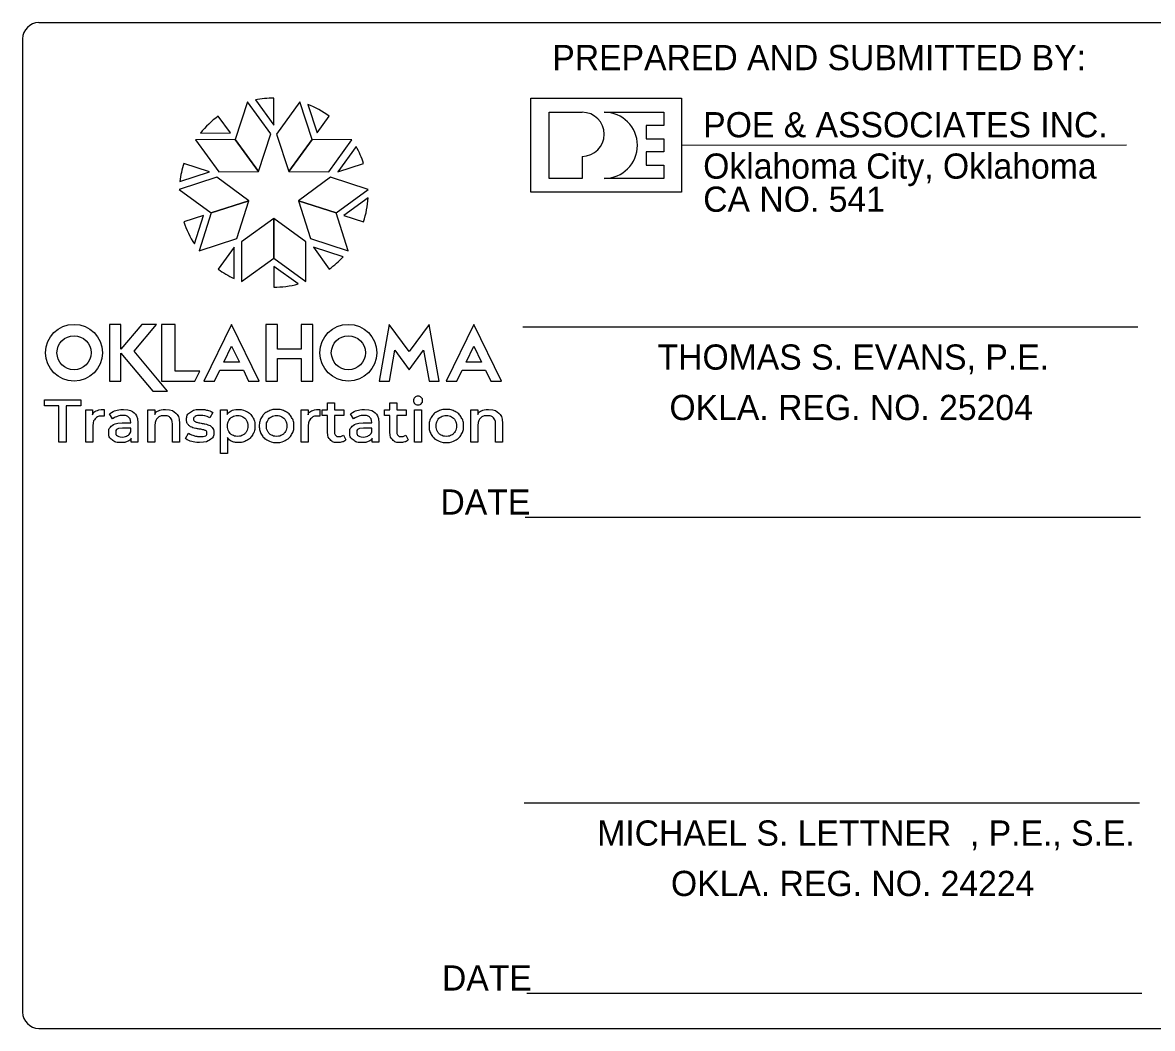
# Model space of a CAD drawing. Extents: x 2121385 to 2181200, y 132498 to 161273.
# Drawn here: x 2158768 to 2164147, y 136441 to 141232 of the extents above; entities that cross this region are included whole.
import ezdxf

# ---------------------------------------------------------------- set-up
doc = ezdxf.new("R2010")
doc.units = 0
for name, color, linetype in [('SHT_Standard_Sheet_Lines', 7, 'Continuous'), ('SHT_Standard_Sheet_Txt', 7, 'Continuous'), ('SHT_Title_Sheet_Misc', 7, 'Continuous')]:
    doc.layers.add(name, color=color, linetype=linetype)

msp = doc.modelspace()

# ---------------------------------------------------------------- linework, layer by layer
at = {"layer": 'SHT_Standard_Sheet_Lines'}
for p, q in [((2158845.7, 141231.8), (2166182.5, 141231.8)), ((2158768.1, 141154.2), (2158768.1, 136518.8)), ((2161149.1, 139783.2), (2164078.2, 139783.2)), ((2161161.2, 138876.8), (2164090.3, 138876.8)), ((2161156.2, 137516), (2164085.4, 137516)), ((2161168.3, 136609.7), (2164097.5, 136609.7)), ((2158845.7, 136441.1), (2166182.5, 136441.1))]:
    msp.add_line(p, q, dxfattribs=at)
for centre, start, end in [((2158845.7, 141154.2), 90, 180), ((2158845.7, 136518.8), 180, 270)]:
    msp.add_arc(centre, 77.6, start, end, dxfattribs=at)
at = {"layer": 'SHT_Standard_Sheet_Txt'}
for p, q in [((2161187.9, 140871.8), (2161904.6, 140871.8)), ((2161187.9, 140423.9), (2161187.9, 140871.8)), ((2161904.6, 140871.8), (2161904.6, 140423.9)), ((2161904.6, 140423.9), (2161187.9, 140423.9))]:
    msp.add_line(p, q, dxfattribs=at)
at = {"layer": 'SHT_Title_Sheet_Misc'}
for p, q in [((2159839, 140854.2), (2159780, 140674.5)), ((2159949.9, 140701.5), (2159839, 140854.2)), ((2159876.5, 140863.3), (2159963.6, 140743.3)), ((2159963.6, 140743.3), (2159963.6, 140871.8)), ((2160088.3, 140854.2), (2159977.5, 140701.1)), ((2160147.3, 140674.5), (2160088.3, 140854.2)), ((2160125.5, 140841.6), (2160170.1, 140706)), ((2159757.2, 140706), (2159699.1, 140785.8)), ((2160170.1, 140706), (2160228.1, 140785.8)), ((2161275, 140804.8), (2161432.5, 140804.8)), ((2161275, 140489.8), (2161275, 140804.8)), ((2161537.5, 140804.8), (2161821, 140804.8)), ((2161821, 140804.8), (2161821, 140741.8)), ((2161821, 140741.8), (2161737, 140741.8)), ((2161737, 140741.8), (2161737, 140678.8)), ((2159780, 140674.5), (2159590.9, 140673.9)), ((2159590.9, 140673.9), (2159701.8, 140521.3)), ((2159614.4, 140705.5), (2159757.2, 140706)), ((2159780, 140674.5), (2159890.9, 140521.9)), ((2159890.9, 140521.9), (2159780, 140674.5)), ((2159890.9, 140521.9), (2159949.9, 140701.5)), ((2159977.5, 140701.1), (2160036.4, 140521.9)), ((2160147.3, 140674.5), (2160036.4, 140521.9)), ((2160036.4, 140521.9), (2160147.3, 140674.5)), ((2160336.4, 140673.9), (2160147.3, 140674.5)), ((2160225.5, 140521.3), (2160336.4, 140673.9)), ((2161737, 140678.8), (2161821, 140678.8)), ((2161821, 140678.8), (2161821, 140615.8)), ((2160356.6, 140641.1), (2160269.5, 140521.1)), ((2161821, 140615.8), (2161737, 140615.8)), ((2161737, 140615.8), (2161737, 140552.8)), ((2161909.1, 140648.7), (2164023.6, 140649.5)), ((2159657.8, 140521.1), (2159535.7, 140560.8)), ((2160269.5, 140521.1), (2160391.6, 140560.8)), ((2161432.5, 140594.8), (2161432.5, 140489.8)), ((2159516.8, 140475.3), (2159657.8, 140521.1)), ((2159701.8, 140521.3), (2159890.9, 140521.9)), ((2160036.4, 140521.9), (2160225.5, 140521.3)), ((2161737, 140552.8), (2161821, 140552.8)), ((2161821, 140552.8), (2161821, 140489.8)), ((2159693.3, 140495.2), (2159513.9, 140436.9)), ((2159846, 140383.5), (2159693.3, 140495.2)), ((2160233.6, 140494.9), (2160081.3, 140383.5)), ((2160413.4, 140436.9), (2160233.6, 140494.9)), ((2161432.5, 140489.8), (2161275, 140489.8)), ((2161821, 140489.8), (2161537.5, 140489.8)), ((2159513.9, 140436.9), (2159666.5, 140325.2)), ((2160260.8, 140325.2), (2160413.4, 140436.9)), ((2159666.5, 140325.2), (2159846, 140383.5)), ((2159846, 140383.5), (2159666.5, 140325.2)), ((2159788.2, 140203.9), (2159846, 140383.5)), ((2160260.8, 140325.2), (2160081.3, 140383.5)), ((2160081.3, 140383.5), (2160139.2, 140203.5)), ((2160081.3, 140383.5), (2160260.8, 140325.2)), ((2160413, 140397.5), (2160297.7, 140313.2)), ((2159629.6, 140313.2), (2159535.7, 140282.7)), ((2159585.9, 140177.3), (2159629.6, 140313.2)), ((2159666.5, 140325.2), (2159608.7, 140145.2)), ((2159963.6, 140298), (2159810.3, 140187.4)), ((2159963.6, 140109.3), (2159963.6, 140298)), ((2160116.6, 140187.6), (2159963.6, 140298)), ((2159963.6, 140298), (2159963.6, 140109.3)), ((2160318.6, 140145.2), (2160260.8, 140325.2)), ((2160297.7, 140313.2), (2160391.6, 140282.7)), ((2159608.7, 140145.2), (2159788.2, 140203.9)), ((2159810.3, 140187.4), (2159810.3, 139998.7)), ((2160117, 139998.7), (2160116.6, 140187.6)), ((2160139.2, 140203.5), (2160318.6, 140145.2)), ((2159774.6, 140161.6), (2159699.1, 140057.7)), ((2159774.6, 140013.4), (2159774.6, 140161.6)), ((2160293.6, 140115.8), (2160152.6, 140161.6)), ((2160152.6, 140161.6), (2160228.1, 140057.7)), ((2159810.3, 139998.7), (2159963.6, 140109.3)), ((2159963.6, 140109.3), (2160117, 139998.7)), ((2160079.5, 139986.9), (2159963.6, 140070.5)), ((2159963.6, 140070.5), (2159963.6, 139971.8)), ((2159235.3, 139794.6), (2159181.3, 139794.6)), ((2159181.3, 139794.6), (2159181.3, 139524.5)), ((2159335.1, 139794.6), (2159235.3, 139675.7)), ((2159235.3, 139675.7), (2159235.3, 139794.6)), ((2159298.5, 139666.9), (2159405.6, 139794.6)), ((2159405.6, 139794.6), (2159335.1, 139794.6)), ((2159429.8, 139794.6), (2159429.8, 139524.5)), ((2159494.7, 139794.6), (2159429.8, 139794.6)), ((2159494.7, 139572), (2159494.7, 139794.6)), ((2159763.2, 139794.6), (2159631.5, 139524.5)), ((2159895, 139524.5), (2159763.2, 139794.6)), ((2159982, 139794.6), (2159925.8, 139794.6)), ((2159925.8, 139794.6), (2159925.8, 139524.5)), ((2159982, 139675.7), (2159982, 139794.6)), ((2160150.5, 139794.6), (2160094.3, 139794.6)), ((2160094.3, 139794.6), (2160094.3, 139675.7)), ((2160150.5, 139524.5), (2160150.5, 139794.6)), ((2160513.5, 139794.6), (2160465.9, 139524.5)), ((2160608.6, 139664.9), (2160513.5, 139794.6)), ((2160703.7, 139794.6), (2160608.6, 139664.9)), ((2160751.4, 139524.5), (2160703.7, 139794.6)), ((2160916.1, 139794.6), (2160784.3, 139524.5)), ((2161047.8, 139524.5), (2160916.1, 139794.6)), ((2159235.3, 139524.5), (2159235.3, 139658.1)), ((2159235.3, 139658.1), (2159387.4, 139476.9)), ((2159457.9, 139476.9), (2159298.5, 139666.9)), ((2159726.3, 139615.2), (2159763.2, 139690.9)), ((2159763.2, 139690.9), (2159800.1, 139615.2)), ((2160094.3, 139675.7), (2159982, 139675.7)), ((2160514.2, 139524.5), (2160540.2, 139671.8)), ((2160540.2, 139671.8), (2160608.6, 139578.5)), ((2160608.6, 139578.5), (2160677.1, 139671.8)), ((2160677.1, 139671.8), (2160703.1, 139524.5)), ((2160879.2, 139615.2), (2160916.1, 139690.9)), ((2160916.1, 139690.9), (2160953, 139615.2)), ((2159800.1, 139615.2), (2159726.3, 139615.2)), ((2159982, 139524.5), (2159982, 139632.5)), ((2159982, 139632.5), (2160094.3, 139632.5)), ((2160094.3, 139632.5), (2160094.3, 139524.5)), ((2160953, 139615.2), (2160879.2, 139615.2)), ((2159611.5, 139572), (2159494.7, 139572)), ((2159588.3, 139524.5), (2159611.5, 139572)), ((2159682.1, 139524.5), (2159707.4, 139576.3)), ((2159707.4, 139576.3), (2159819.1, 139576.3)), ((2159819.1, 139576.3), (2159844.4, 139524.5)), ((2160834.9, 139524.5), (2160860.2, 139576.3)), ((2160860.2, 139576.3), (2160971.9, 139576.3)), ((2160971.9, 139576.3), (2160997.2, 139524.5)), ((2159181.3, 139524.5), (2159235.3, 139524.5)), ((2159429.8, 139524.5), (2159588.3, 139524.5)), ((2159631.5, 139524.5), (2159682.1, 139524.5)), ((2159844.4, 139524.5), (2159895, 139524.5)), ((2159925.8, 139524.5), (2159982, 139524.5)), ((2160094.3, 139524.5), (2160150.5, 139524.5)), ((2160465.9, 139524.5), (2160514.2, 139524.5)), ((2160703.1, 139524.5), (2160751.4, 139524.5)), ((2160784.3, 139524.5), (2160834.9, 139524.5)), ((2160997.2, 139524.5), (2161047.8, 139524.5)), ((2159387.4, 139476.9), (2159457.9, 139476.9))]:
    msp.add_line(p, q, dxfattribs=at)
for points in [[(2158941.3, 139405.7), (2158872.3, 139405.7), (2158872.3, 139435.8), (2159044.7, 139435.8), (2159044.7, 139405.7), (2158975.7, 139405.7), (2158975.7, 139233.3), (2158941.3, 139233.3), (2158941.3, 139405.7)], [(2159102.6, 139310.5), (2159102.6, 139233.3), (2159069, 139233.3), (2159069, 139388), (2159101.4, 139388), (2159101.4, 139363.2)], [(2159156.9, 139389.4), (2159156.9, 139357.6)], [(2159398.2, 139313), (2159398.2, 139233.3), (2159364.6, 139233.3), (2159364.6, 139388), (2159397, 139388), (2159397, 139365.7)], [(2159743.8, 139255.8), (2159743.8, 139178.7), (2159710.2, 139178.7), (2159710.2, 139388), (2159742.6, 139388), (2159742.6, 139364.6)], [(2160128.3, 139310.5), (2160128.3, 139233.3), (2160094.7, 139233.3), (2160094.7, 139388), (2160127.1, 139388), (2160127.1, 139363.2)], [(2160182.6, 139389.4), (2160182.6, 139357.6)], [(2160219.5, 139281.2), (2160219.5, 139360.2), (2160193.6, 139360.2), (2160193.6, 139388), (2160219.5, 139388), (2160219.5, 139420.6), (2160253, 139420.6), (2160253, 139388), (2160296.8, 139388), (2160296.8, 139360.2), (2160253, 139360.2), (2160253, 139282.3)], [(2160516.3, 139281.2), (2160516.3, 139360.2), (2160490.4, 139360.2), (2160490.4, 139388), (2160516.3, 139388), (2160516.3, 139420.6), (2160549.8, 139420.6), (2160549.8, 139388), (2160593.6, 139388), (2160593.6, 139360.2), (2160549.8, 139360.2), (2160549.8, 139282.3)], [(2160634.2, 139388), (2160667.7, 139388), (2160667.7, 139233.3), (2160634.2, 139233.3), (2160634.2, 139388)], [(2160936.3, 139313), (2160936.3, 139233.3), (2160902.8, 139233.3), (2160902.8, 139388), (2160935.2, 139388), (2160935.2, 139365.7)], [(2159195.9, 139344.4), (2159182.3, 139368.2)], [(2159242.2, 139324.7), (2159282.9, 139324.7), (2159282.9, 139327.3)], [(2159316.5, 139326.2), (2159316.5, 139233.3), (2159284.4, 139233.3), (2159284.4, 139253)], [(2159515.2, 139322), (2159515.2, 139233.3), (2159481.7, 139233.3), (2159481.7, 139318.9)], [(2159674, 139374), (2159660.3, 139348.9)], [(2160343.6, 139344.4), (2160329.9, 139368.2)], [(2160389.8, 139324.7), (2160430.6, 139324.7), (2160430.6, 139327.3)], [(2160464.1, 139326.2), (2160464.1, 139233.3), (2160432, 139233.3), (2160432, 139253)], [(2161053.4, 139322), (2161053.4, 139233.3), (2161019.8, 139233.3), (2161019.8, 139318.9)], [(2159282.9, 139282.3), (2159282.9, 139299.7), (2159243.3, 139299.7)], [(2159544.1, 139251.1), (2159557.5, 139276.2)], [(2160430.6, 139282.3), (2160430.6, 139299.7), (2160391, 139299.7)], [(2160296.7, 139267.2), (2160307.1, 139244.1)], [(2160593.5, 139267.2), (2160603.9, 139244.1)]]:
    msp.add_lwpolyline(points, dxfattribs=at)
for centre, radius in [((2159012.8, 139659.5), 135.1), ((2160319, 139659.5), 135.1), ((2159012.8, 139659.5), 81), ((2160319, 139659.5), 81)]:
    msp.add_circle(centre, radius, dxfattribs=at)
for centre, radius, start, end in [((2159963.6, 140421.8), 450, 90, 101.1654), ((2159963.6, 140421.8), 450, 54, 68.9132), ((2159963.6, 140421.8), 450, 126, 140.9132), ((2161432.5, 140699.8), 105, 270, 90), ((2161537.5, 140647.3), 157.5, 270, 90), ((2159963.6, 140421.8), 450, 18, 29.1654), ((2159963.6, 140421.8), 450, 162, 173.1654), ((2159963.6, 140421.8), 450, 342, 356.9132), ((2159963.6, 140421.8), 450, 198, 212.9132), ((2159963.6, 140421.8), 450, 306, 317.1654), ((2159963.6, 140421.8), 450, 234, 245.1654), ((2159963.6, 140421.8), 450, 270, 284.9132)]:
    msp.add_arc(centre, radius, start, end, dxfattribs=at)
for points in [[(2160651, 139411.1), (2160641.7, 139411.1), (2160635.5, 139417), (2160629.3, 139422.9), (2160629.3, 139431.4), (2160629.3, 139439.8), (2160635.5, 139445.8), (2160641.6, 139451.9), (2160651, 139451.9), (2160660.2, 139451.9), (2160666.4, 139446.1), (2160672.6, 139440.4), (2160672.6, 139432), (2160672.6, 139423.2), (2160666.5, 139417.1), (2160660.3, 139411.1), (2160651, 139411.1)], [(2159101.4, 139363.2), (2159103.4, 139375.2), (2159118.2, 139382.3), (2159133.1, 139389.4), (2159156.9, 139389.4)], [(2159182.3, 139368.2), (2159195.6, 139379.3), (2159212.5, 139384.3), (2159229.4, 139389.4), (2159248.2, 139389.4)], [(2159248.2, 139389.4), (2159281.1, 139389.4), (2159298.8, 139373.4), (2159316.5, 139357.4), (2159316.5, 139326.2)], [(2159397, 139365.7), (2159400.4, 139376.4), (2159415.3, 139382.9), (2159430.3, 139389.4), (2159449, 139389.4)], [(2159449, 139389.4), (2159479.2, 139389.4), (2159497.2, 139372.1), (2159515.2, 139354.8), (2159515.2, 139322)], [(2159557.5, 139276.2), (2159570.1, 139268.7), (2159584, 139264.6), (2159597.8, 139260.6), (2159612.1, 139260.6), (2159645.4, 139260.6), (2159645.4, 139278.1), (2159645.4, 139283.5), (2159641.3, 139286.7), (2159637.2, 139290), (2159630.2, 139291.8), (2159623.2, 139293.5), (2159609.2, 139295.8), (2159591.5, 139298.6), (2159579.2, 139302.4), (2159567, 139306.2), (2159558, 139315.6), (2159549, 139325), (2159549, 139342), (2159549, 139363.5), (2159567.3, 139376.5), (2159585.5, 139389.4), (2159615.5, 139389.4), (2159631.1, 139389.4), (2159646.8, 139385.7), (2159662.4, 139381.9), (2159674, 139374)], [(2159742.6, 139364.6), (2159746.9, 139376.2), (2159761.6, 139382.8), (2159776.4, 139389.4), (2159794, 139389.4)], [(2159794, 139389.4), (2159816.9, 139389.4), (2159835.2, 139379.4), (2159853.4, 139369.5), (2159863.7, 139351.7), (2159874, 139333.8), (2159874, 139310.7), (2159874, 139287.5), (2159863.7, 139269.5), (2159853.4, 139251.5), (2159835.1, 139241.5), (2159816.9, 139231.6), (2159794, 139231.6), (2159776.9, 139231.6), (2159762.6, 139238.1), (2159748.4, 139244.5), (2159743.8, 139255.8)], [(2159977.4, 139231.6), (2159953.9, 139231.6), (2159935.1, 139241.8), (2159916.3, 139252), (2159905.7, 139270), (2159895.1, 139288), (2159895.1, 139310.7), (2159895.1, 139333.4), (2159905.7, 139351.3), (2159916.3, 139369.2), (2159935.1, 139379.3), (2159953.9, 139389.4), (2159977.4, 139389.4), (2160000.9, 139389.4), (2160019.6, 139379.3), (2160038.3, 139369.2), (2160048.9, 139351.3), (2160059.5, 139333.3), (2160059.5, 139310.7), (2160059.5, 139288.1), (2160048.9, 139270), (2160038.2, 139252), (2160019.6, 139241.8), (2160000.9, 139231.6), (2159977.4, 139231.6)], [(2160127.1, 139363.2), (2160129.1, 139375.2), (2160143.9, 139382.3), (2160158.8, 139389.4), (2160182.6, 139389.4)], [(2160329.9, 139368.2), (2160343.2, 139379.3), (2160360.1, 139384.3), (2160377, 139389.4), (2160395.9, 139389.4)], [(2160395.9, 139389.4), (2160428.7, 139389.4), (2160446.4, 139373.4), (2160464.1, 139357.4), (2160464.1, 139326.2)], [(2160785.5, 139231.6), (2160761.9, 139231.6), (2160743.2, 139241.8), (2160724.4, 139252), (2160713.8, 139270), (2160703.1, 139288), (2160703.1, 139310.7), (2160703.1, 139333.4), (2160713.7, 139351.3), (2160724.3, 139369.2), (2160743.1, 139379.3), (2160762, 139389.4), (2160785.5, 139389.4), (2160809, 139389.4), (2160827.6, 139379.3), (2160846.3, 139369.2), (2160856.9, 139351.3), (2160867.5, 139333.3), (2160867.5, 139310.7), (2160867.5, 139288.1), (2160856.9, 139270), (2160846.3, 139252), (2160827.6, 139241.8), (2160809, 139231.6), (2160785.5, 139231.6)], [(2160935.2, 139365.7), (2160938.5, 139376.4), (2160953.4, 139382.9), (2160968.4, 139389.4), (2160987.1, 139389.4)], [(2160987.1, 139389.4), (2161017.4, 139389.4), (2161035.4, 139372.1), (2161053.4, 139354.8), (2161053.4, 139322)], [(2159156.9, 139357.6), (2159151.2, 139357.9), (2159147.6, 139357.9), (2159126.5, 139357.9), (2159114.5, 139345.7), (2159102.6, 139333.5), (2159102.6, 139310.5)], [(2159284.4, 139253), (2159282.4, 139243.1), (2159268.9, 139237.4), (2159255.5, 139231.6), (2159237.3, 139231.6), (2159210.6, 139231.6), (2159194.3, 139244.4), (2159178, 139257.3), (2159178, 139278.4), (2159178, 139299.3), (2159193.6, 139312), (2159209.2, 139324.7), (2159242.2, 139324.7)], [(2159282.9, 139327.3), (2159282.9, 139343.4), (2159273.5, 139351.9), (2159264, 139360.5), (2159245.1, 139360.5), (2159232.1, 139360.5), (2159219.6, 139356.3), (2159207.2, 139352.1), (2159195.9, 139344.4)], [(2159481.7, 139318.9), (2159481.7, 139339.3), (2159471.9, 139349.5), (2159462, 139359.6), (2159443.5, 139359.6), (2159422.4, 139359.6), (2159410.3, 139347.7), (2159398.2, 139335.7), (2159398.2, 139313)], [(2159660.3, 139348.9), (2159639.7, 139360.7), (2159615.3, 139360.7), (2159598.6, 139360.7), (2159590.4, 139355.8), (2159582.3, 139350.8), (2159582.3, 139343.1), (2159582.3, 139336.9), (2159586.7, 139333.3), (2159591.1, 139329.7), (2159598.4, 139327.9), (2159605.7, 139326), (2159617, 139323.8), (2159637.9, 139320.4), (2159649.7, 139316.7), (2159661.5, 139313.1), (2159670.2, 139303.9), (2159678.9, 139294.8), (2159678.9, 139278.7), (2159678.9, 139256.9), (2159660.2, 139244.2), (2159641.5, 139231.6), (2159610.1, 139231.6)], [(2159791.7, 139260.8), (2159805.5, 139260.8), (2159816.4, 139267), (2159827.4, 139273.3), (2159833.8, 139284.6), (2159840.2, 139296), (2159840.2, 139310.7), (2159840.2, 139325.4), (2159833.8, 139336.7), (2159827.4, 139348), (2159816.5, 139354.1), (2159805.5, 139360.2), (2159791.7, 139360.2), (2159778.2, 139360.2), (2159767.2, 139353.9), (2159756.2, 139347.7), (2159749.8, 139336.6), (2159743.5, 139325.5), (2159743.5, 139310.7), (2159743.5, 139295.9), (2159749.7, 139284.5), (2159756, 139273.2), (2159767, 139267), (2159778.1, 139260.8), (2159791.7, 139260.8)], [(2159977.4, 139260.8), (2159991.2, 139260.8), (2160002.2, 139267), (2160013.1, 139273.2), (2160019.4, 139284.6), (2160025.7, 139295.9), (2160025.7, 139310.7), (2160025.7, 139325.4), (2160019.4, 139336.7), (2160013.2, 139348), (2160002.2, 139354.1), (2159991.3, 139360.2), (2159977.4, 139360.2), (2159963.6, 139360.2), (2159952.6, 139354.1), (2159941.7, 139348), (2159935.3, 139336.7), (2159928.9, 139325.5), (2159928.9, 139310.7), (2159928.9, 139295.9), (2159935.3, 139284.6), (2159941.7, 139273.2), (2159952.7, 139267), (2159963.6, 139260.8), (2159977.4, 139260.8)], [(2160182.6, 139357.6), (2160176.9, 139357.9), (2160173.3, 139357.9), (2160152.2, 139357.9), (2160140.2, 139345.7), (2160128.3, 139333.5), (2160128.3, 139310.5)], [(2160432, 139253), (2160430.1, 139243.1), (2160416.6, 139237.4), (2160403.1, 139231.6), (2160385, 139231.6), (2160358.3, 139231.6), (2160341.9, 139244.4), (2160325.6, 139257.3), (2160325.6, 139278.4), (2160325.6, 139299.3), (2160341.2, 139312), (2160356.8, 139324.7), (2160389.8, 139324.7)], [(2160430.6, 139327.3), (2160430.6, 139343.4), (2160421.1, 139351.9), (2160411.6, 139360.5), (2160392.7, 139360.5), (2160379.7, 139360.5), (2160367.3, 139356.3), (2160354.9, 139352.1), (2160343.6, 139344.4)], [(2160785.5, 139260.8), (2160799.3, 139260.8), (2160810.2, 139267), (2160821.1, 139273.2), (2160827.4, 139284.6), (2160833.7, 139295.9), (2160833.7, 139310.7), (2160833.7, 139325.4), (2160827.5, 139336.7), (2160821.2, 139348), (2160810.3, 139354.1), (2160799.3, 139360.2), (2160785.5, 139360.2), (2160771.6, 139360.2), (2160760.7, 139354.1), (2160749.7, 139348), (2160743.3, 139336.7), (2160737, 139325.5), (2160737, 139310.7), (2160737, 139295.9), (2160743.4, 139284.6), (2160749.8, 139273.2), (2160760.7, 139267), (2160771.6, 139260.8), (2160785.5, 139260.8)], [(2161019.8, 139318.9), (2161019.8, 139339.3), (2161010, 139349.5), (2161000.2, 139359.6), (2160981.7, 139359.6), (2160960.5, 139359.6), (2160948.4, 139347.7), (2160936.3, 139335.7), (2160936.3, 139313)], [(2159243.3, 139299.7), (2159211.2, 139299.7), (2159211.2, 139279.5), (2159211.2, 139269.5), (2159219.2, 139263.8), (2159227.1, 139258), (2159241.9, 139258)], [(2159241.9, 139258), (2159256.9, 139258), (2159267.6, 139264.4), (2159278.3, 139270.9), (2159282.9, 139282.3)], [(2160307.1, 139244.1), (2160299.5, 139237.2), (2160290.2, 139234.4), (2160280.8, 139231.6), (2160270.8, 139231.6), (2160246.5, 139231.6), (2160233, 139244.5), (2160219.5, 139257.5), (2160219.5, 139281.2)], [(2160253, 139282.3), (2160253, 139271.2), (2160258.4, 139265.6), (2160263.7, 139260), (2160273.9, 139260), (2160285.5, 139260), (2160296.7, 139267.2)], [(2160391, 139299.7), (2160358.9, 139299.7), (2160358.9, 139279.5), (2160358.9, 139269.5), (2160366.8, 139263.8), (2160374.7, 139258), (2160389.6, 139258)], [(2160389.6, 139258), (2160404.5, 139258), (2160415.2, 139264.4), (2160425.9, 139270.9), (2160430.6, 139282.3)], [(2160603.9, 139244.1), (2160596.3, 139237.2), (2160587, 139234.4), (2160577.6, 139231.6), (2160567.6, 139231.6), (2160543.3, 139231.6), (2160529.8, 139244.5), (2160516.3, 139257.5), (2160516.3, 139281.2)], [(2160549.8, 139282.3), (2160549.8, 139271.2), (2160555.2, 139265.6), (2160560.5, 139260), (2160570.7, 139260), (2160582.3, 139260), (2160593.5, 139267.2)], [(2159610.1, 139231.6), (2159590.9, 139231.6), (2159573.2, 139236.7), (2159555.5, 139241.7), (2159544.1, 139251.1)]]:
    msp.add_open_spline(points, degree=3, dxfattribs=at)

# ---------------------------------------------------------------- texts
at = {"layer": 'SHT_Standard_Sheet_Txt'}
for s, p in [('PREPARED AND SUBMITTED BY:', (2161290, 141005.2)), ('POE & ASSOCIATES INC.', (2162008.5, 140685.4)), ('Oklahoma City, Oklahoma', (2162008.5, 140488.4)), ('CA NO. 541', (2162008.5, 140330.7)), ('THOMAS S. EVANS, P.E.', (2161791.3, 139578.8)), ('OKLA. REG. NO. 25204', (2161847.8, 139338.8)), ('DATE', (2160757.6, 138888.5)), ('MICHAEL S. LETTNER  , P.E., S.E.', (2161504.1, 137311.7)), ('OKLA. REG. NO. 24224', (2161854.9, 137071.7)), ('DATE', (2160764.7, 136621.4))]:
    msp.add_text(s, height=120, dxfattribs=at).set_placement(p)

doc.saveas('drawing.dxf')
